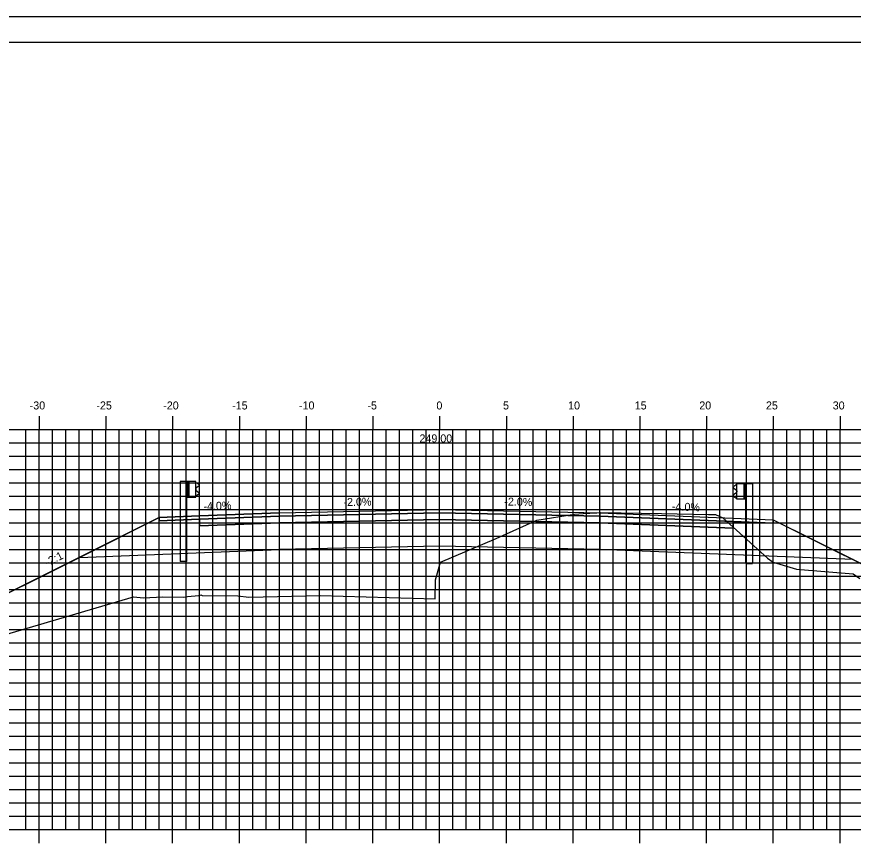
# Model space of a CAD drawing. Extents: x -22 to 1480, y -1511 to 8.
# Drawn here: x 378.2 to 440.9, y -1463.6 to -1401.4 of the extents above; entities that cross this region are included whole.
import ezdxf

# ---------------------------------------------------------------- set-up
doc = ezdxf.new("R2010")
doc.units = 0
for name, color, linetype in [('ANNOTATION', 7, 'Continuous'), ('BORDER', 7, 'Continuous'), ('D_Guardrail_Beam_Lt', 7, 'Continuous'), ('D_Guardrail_Beam_Rt', 7, 'Continuous'), ('D_Roadway_Centerline', 7, 'Continuous'), ('D_Roadway_Centerline_Text', 7, 'Continuous'), ('D_Roadway_Edge_Shoulder', 7, 'Continuous'), ('D_Roadway_Edge_TW', 7, 'Continuous'), ('D_Roadway_Pavement', 7, 'Continuous'), ('D_Roadway_SlopeLines', 7, 'Continuous'), ('D_Roadway_SubGrade', 7, 'Continuous'), ('H_V ANNOTATION', 7, 'Continuous'), ('MAJOR', 7, 'Continuous'), ('MINOR', 7, 'Continuous'), ('PLOT BOUNDARY', 7, 'Continuous'), ('S_Roadway_Centerline', 7, 'Continuous')]:
    doc.layers.add(name, color=color, linetype=linetype)

msp = doc.modelspace()

# ---------------------------------------------------------------- linework, layer by layer
at = {"layer": 'BORDER'}
msp.add_line((494.913, -1403.331), (334.913, -1403.331), dxfattribs=at)
at = {"layer": 'D_Guardrail_Beam_Lt'}
for p, q in [((390.484, -1436.23), (390.484, -1442.23)), ((390.955, -1436.23), (390.484, -1436.23)), ((391.642, -1436.23), (390.955, -1436.23)), ((390.955, -1436.23), (390.955, -1437.397)), ((391.017, -1436.23), (391.017, -1437.397)), ((391.121, -1436.23), (391.121, -1437.397)), ((391.642, -1437.397), (391.642, -1436.23)), ((391.642, -1436.314), (391.716, -1436.328)), ((391.732, -1436.335), (391.876, -1436.435)), ((391.647, -1436.778), (391.647, -1436.849)), ((391.876, -1436.578), (391.68, -1436.714)), ((391.68, -1436.913), (391.876, -1437.049)), ((390.955, -1437.397), (391.642, -1437.397)), ((390.975, -1442.23), (390.975, -1437.397)), ((391.716, -1437.299), (391.642, -1437.314)), ((391.876, -1437.192), (391.732, -1437.292)), ((390.975, -1442.23), (390.484, -1442.23))]:
    msp.add_line(p, q, dxfattribs=at)
for centre, major_axis, start_param, end_param in [((391.708, -1436.369), (0.0417, 0), 0.959931, 1.376053), ((391.725, -1436.778), (-0.0789, 0), 5.323254, 6.283185), ((391.725, -1436.849), (-0.0789, 0), 6.283185, 7.243116), ((391.825, -1436.506), (0.0877, 0), 5.323254, 7.243116), ((391.708, -1437.258), (0.0417, 0), 4.907132, 5.323254), ((391.825, -1437.121), (0.0877, 0), 5.323254, 7.243116)]:
    msp.add_ellipse(centre, major_axis=major_axis, ratio=0.995501, start_param=start_param, end_param=end_param, dxfattribs=at)
at = {"layer": 'D_Guardrail_Beam_Rt'}
for p, q in [((432.184, -1436.39), (432.871, -1436.39)), ((432.184, -1437.557), (432.184, -1436.39)), ((432.705, -1436.39), (432.705, -1437.557)), ((432.809, -1436.39), (432.809, -1437.557)), ((432.871, -1436.39), (433.342, -1436.39)), ((432.871, -1436.39), (432.871, -1437.557)), ((433.342, -1436.39), (433.342, -1442.39)), ((432.094, -1436.495), (431.95, -1436.595)), ((431.95, -1436.738), (432.146, -1436.874)), ((432.184, -1436.474), (432.11, -1436.488)), ((432.179, -1436.938), (432.179, -1437.009)), ((432.146, -1437.073), (431.95, -1437.209)), ((431.95, -1437.352), (432.094, -1437.452)), ((432.11, -1437.459), (432.184, -1437.474)), ((432.871, -1437.557), (432.184, -1437.557)), ((432.85, -1442.39), (432.85, -1437.557)), ((432.85, -1442.39), (433.342, -1442.39))]:
    msp.add_line(p, q, dxfattribs=at)
for centre, major_axis, start_param, end_param in [((432.001, -1436.666), (-0.0877, 0), 5.323254, 7.243116), ((432.118, -1436.529), (-0.0417, 0), 4.907132, 5.323254), ((432.1, -1436.938), (0.0789, 0), 0, 0.959931), ((432.1, -1437.009), (0.0789, 0), 5.323254, 6.283185), ((432.001, -1437.281), (-0.0877, 0), 5.323254, 7.243116), ((432.118, -1437.418), (-0.0417, 0), 0.959931, 1.376053)]:
    msp.add_ellipse(centre, major_axis=major_axis, ratio=0.995501, start_param=start_param, end_param=end_param, dxfattribs=at)
at = {"layer": 'D_Roadway_Centerline'}
msp.add_lwpolyline([(356.625, -1455.077), (360.465, -1453.158), (371.429, -1447.676), (374.305, -1446.237), (382.935, -1441.923), (388.913, -1438.934), (391.913, -1438.814), (397.913, -1438.574), (409.913, -1438.334), (421.913, -1438.574), (431.913, -1438.974), (434.913, -1439.094), (440.891, -1442.083), (456.487, -1449.881)], dxfattribs=at)
at = {"layer": 'D_Roadway_Edge_Shoulder'}
for points in [[(397.913, -1438.574), (391.913, -1438.814), (391.913, -1438.814), (388.913, -1438.934), (388.913, -1439.184), (391.913, -1439.064), (391.913, -1439.064), (397.913, -1438.824)], [(421.913, -1438.574), (431.913, -1438.974), (431.913, -1438.974), (434.913, -1439.094), (434.913, -1439.344), (431.913, -1439.224), (431.913, -1439.224), (421.913, -1438.824)]]:
    msp.add_lwpolyline(points, close=True, dxfattribs=at)
at = {"layer": 'D_Roadway_Edge_TW'}
msp.add_lwpolyline([(397.913, -1438.824), (397.913, -1438.574), (409.913, -1438.334), (421.913, -1438.574), (421.913, -1438.824), (409.913, -1438.584)], close=True, dxfattribs=at)
at = {"layer": 'D_Roadway_Pavement'}
for points in [[(397.913, -1438.824), (391.913, -1439.064), (391.913, -1439.064), (391.913, -1439.564), (397.913, -1439.324), (397.913, -1438.824)], [(421.913, -1438.824), (431.913, -1439.224), (431.913, -1439.224), (431.913, -1439.724), (421.913, -1439.324), (421.913, -1438.824)]]:
    msp.add_lwpolyline(points, dxfattribs=at)
msp.add_lwpolyline([(397.913, -1439.324), (397.913, -1438.824), (409.913, -1438.584), (421.913, -1438.824), (421.913, -1439.324), (409.913, -1439.084)], close=True, dxfattribs=at)
at = {"layer": 'D_Roadway_SlopeLines'}
for points in [[(388.913, -1438.934), (356.625, -1455.077)], [(434.913, -1439.094), (456.487, -1449.881)]]:
    msp.add_lwpolyline(points, dxfattribs=at)
at = {"layer": 'D_Roadway_SubGrade'}
for points in [[(397.913, -1439.324), (391.913, -1439.564), (391.913, -1439.064), (388.913, -1439.184), (388.913, -1438.934), (382.935, -1441.923), (397.913, -1441.324)], [(397.913, -1441.324), (397.913, -1439.324), (409.913, -1439.084), (421.913, -1439.324), (421.913, -1441.324), (409.913, -1441.084)], [(421.913, -1439.324), (431.913, -1439.724), (431.913, -1439.224), (434.913, -1439.344), (434.913, -1439.094), (440.891, -1442.083), (421.913, -1441.324)]]:
    msp.add_lwpolyline(points, close=True, dxfattribs=at)
at = {"layer": 'MAJOR'}
for p, q in [((379.913, -1431.329), (379.913, -1432.331)), ((384.913, -1431.329), (384.913, -1432.331)), ((389.913, -1431.329), (389.913, -1432.331)), ((394.913, -1431.329), (394.913, -1432.331)), ((399.913, -1431.329), (399.913, -1432.331)), ((404.913, -1431.329), (404.913, -1432.331)), ((409.913, -1431.329), (409.913, -1432.331)), ((414.913, -1431.329), (414.913, -1432.331)), ((419.913, -1431.329), (419.913, -1432.331)), ((424.913, -1431.329), (424.913, -1432.331)), ((429.913, -1431.329), (429.913, -1432.331)), ((434.913, -1431.329), (434.913, -1432.331)), ((439.913, -1431.329), (439.913, -1432.331)), ((339.913, -1432.331), (479.913, -1432.331)), ((339.913, -1432.331), (479.913, -1432.331)), ((379.913, -1462.331), (379.913, -1432.331)), ((384.913, -1462.331), (384.913, -1432.331)), ((389.913, -1462.331), (389.913, -1432.331)), ((394.913, -1462.331), (394.913, -1432.331)), ((399.913, -1462.331), (399.913, -1432.331)), ((404.913, -1462.331), (404.913, -1432.331)), ((409.913, -1462.331), (409.913, -1432.331)), ((414.913, -1462.331), (414.913, -1432.331)), ((419.913, -1462.331), (419.913, -1432.331)), ((424.913, -1462.331), (424.913, -1432.331)), ((429.913, -1462.331), (429.913, -1432.331)), ((434.913, -1462.331), (434.913, -1432.331)), ((439.913, -1462.331), (439.913, -1432.331)), ((339.913, -1437.331), (479.913, -1437.331)), ((339.913, -1442.331), (479.913, -1442.331)), ((339.913, -1447.331), (479.913, -1447.331)), ((339.913, -1452.331), (479.913, -1452.331)), ((339.913, -1457.331), (479.913, -1457.331)), ((339.913, -1462.331), (479.913, -1462.331)), ((339.913, -1462.331), (479.913, -1462.331)), ((379.913, -1463.333), (379.913, -1462.331)), ((384.913, -1463.333), (384.913, -1462.331)), ((389.913, -1463.333), (389.913, -1462.331)), ((394.913, -1463.333), (394.913, -1462.331)), ((399.913, -1463.333), (399.913, -1462.331)), ((404.913, -1463.333), (404.913, -1462.331)), ((409.913, -1463.333), (409.913, -1462.331)), ((414.913, -1463.333), (414.913, -1462.331)), ((419.913, -1463.333), (419.913, -1462.331)), ((424.913, -1463.333), (424.913, -1462.331)), ((429.913, -1463.333), (429.913, -1462.331)), ((434.913, -1463.333), (434.913, -1462.331)), ((439.913, -1463.333), (439.913, -1462.331))]:
    msp.add_line(p, q, dxfattribs=at)
at = {"layer": 'MINOR'}
for p, q in [((378.913, -1462.331), (378.913, -1432.331)), ((380.913, -1462.331), (380.913, -1432.331)), ((381.913, -1462.331), (381.913, -1432.331)), ((382.913, -1462.331), (382.913, -1432.331)), ((383.913, -1462.331), (383.913, -1432.331)), ((385.913, -1462.331), (385.913, -1432.331)), ((386.913, -1462.331), (386.913, -1432.331)), ((387.913, -1462.331), (387.913, -1432.331)), ((388.913, -1462.331), (388.913, -1432.331)), ((390.913, -1462.331), (390.913, -1432.331)), ((391.913, -1462.331), (391.913, -1432.331)), ((392.913, -1462.331), (392.913, -1432.331)), ((393.913, -1462.331), (393.913, -1432.331)), ((395.913, -1462.331), (395.913, -1432.331)), ((396.913, -1462.331), (396.913, -1432.331)), ((397.913, -1462.331), (397.913, -1432.331)), ((398.913, -1462.331), (398.913, -1432.331)), ((400.913, -1462.331), (400.913, -1432.331)), ((401.913, -1462.331), (401.913, -1432.331)), ((402.913, -1462.331), (402.913, -1432.331)), ((403.913, -1462.331), (403.913, -1432.331)), ((405.913, -1462.331), (405.913, -1432.331)), ((406.913, -1462.331), (406.913, -1432.331)), ((407.913, -1462.331), (407.913, -1432.331)), ((408.913, -1462.331), (408.913, -1432.331)), ((410.913, -1462.331), (410.913, -1432.331)), ((411.913, -1462.331), (411.913, -1432.331)), ((412.913, -1462.331), (412.913, -1432.331)), ((413.913, -1462.331), (413.913, -1432.331)), ((415.913, -1462.331), (415.913, -1432.331)), ((416.913, -1462.331), (416.913, -1432.331)), ((417.913, -1462.331), (417.913, -1432.331)), ((418.913, -1462.331), (418.913, -1432.331)), ((420.913, -1462.331), (420.913, -1432.331)), ((421.913, -1462.331), (421.913, -1432.331)), ((422.913, -1462.331), (422.913, -1432.331)), ((423.913, -1462.331), (423.913, -1432.331)), ((425.913, -1462.331), (425.913, -1432.331)), ((426.913, -1462.331), (426.913, -1432.331)), ((427.913, -1462.331), (427.913, -1432.331)), ((428.913, -1462.331), (428.913, -1432.331)), ((430.913, -1462.331), (430.913, -1432.331)), ((431.913, -1462.331), (431.913, -1432.331)), ((432.913, -1462.331), (432.913, -1432.331)), ((433.913, -1462.331), (433.913, -1432.331)), ((435.913, -1462.331), (435.913, -1432.331)), ((436.913, -1462.331), (436.913, -1432.331)), ((437.913, -1462.331), (437.913, -1432.331)), ((438.913, -1462.331), (438.913, -1432.331)), ((339.913, -1433.331), (479.913, -1433.331)), ((339.913, -1434.331), (479.913, -1434.331)), ((339.913, -1435.331), (479.913, -1435.331)), ((339.913, -1436.331), (479.913, -1436.331)), ((339.913, -1438.331), (479.913, -1438.331)), ((339.913, -1439.331), (479.913, -1439.331)), ((339.913, -1440.331), (479.913, -1440.331)), ((339.913, -1441.331), (479.913, -1441.331)), ((339.913, -1443.331), (479.913, -1443.331)), ((339.913, -1444.331), (479.913, -1444.331)), ((339.913, -1445.331), (479.913, -1445.331)), ((339.913, -1446.331), (479.913, -1446.331)), ((339.913, -1448.331), (479.913, -1448.331)), ((339.913, -1449.331), (479.913, -1449.331)), ((339.913, -1450.331), (479.913, -1450.331)), ((339.913, -1451.331), (479.913, -1451.331)), ((339.913, -1453.331), (479.913, -1453.331)), ((339.913, -1454.331), (479.913, -1454.331)), ((339.913, -1455.331), (479.913, -1455.331)), ((339.913, -1456.331), (479.913, -1456.331)), ((339.913, -1458.331), (479.913, -1458.331)), ((339.913, -1459.331), (479.913, -1459.331)), ((339.913, -1460.331), (479.913, -1460.331)), ((339.913, -1461.331), (479.913, -1461.331))]:
    msp.add_line(p, q, dxfattribs=at)
at = {"layer": 'PLOT BOUNDARY'}
msp.add_lwpolyline([(326.82, -1511.39), (496.82, -1511.39), (496.82, -1401.39), (326.82, -1401.39)], close=True, dxfattribs=at)
at = {"layer": 'S_Roadway_Centerline'}
msp.add_lwpolyline([(373.809, -1448.744), (386.991, -1444.884), (387.733, -1444.948), (389.169, -1444.89), (390.759, -1444.901), (391.027, -1444.865), (391.871, -1444.778), (391.927, -1444.742), (391.972, -1444.741), (392.014, -1444.729), (392.133, -1444.772), (394.786, -1444.799), (395.627, -1444.898), (400.975, -1444.777), (409.584, -1445.021), (409.601, -1443.6), (409.991, -1442.29), (414.137, -1440.499), (417.196, -1439.136), (420.015, -1438.677), (420.67, -1438.635), (421.692, -1438.569), (421.983, -1438.55), (426.53, -1438.643), (430.049, -1438.704), (430.592, -1438.711), (431.136, -1438.945), (434.478, -1441.973), (434.894, -1442.291), (436.64, -1442.813), (440.884, -1443.152), (441.391, -1443.513)], dxfattribs=at)

# ---------------------------------------------------------------- texts
at = {"layer": 'ANNOTATION'}
for s, rotation, p in [('-2.0%', 1.14576, (402.716, -1438.077)), ('-2.0%', 358.85424, (414.756, -1438.03)), ('-4.0%', 2.29061, (392.229, -1438.4)), ('-4.0%', 357.70939, (427.309, -1438.389)), ('-2:1', 26.56505, (380.538, -1442.603))]:
    msp.add_text(s, height=0.6, rotation=rotation, dxfattribs=at).set_placement(p)
at = {"layer": 'D_Roadway_Centerline'}
for s, p in [('C', (409.908, -1438.334)), ('L', (409.913, -1438.341))]:
    msp.add_text(s, height=0.0146, dxfattribs=at).set_placement(p)
at = {"layer": 'D_Roadway_Centerline_Text'}
msp.add_text('249.00', height=0.6, dxfattribs=at).set_placement((408.404, -1433.302))
at = {"layer": 'H_V ANNOTATION'}
for s, p in [('-30', (379.201, -1430.831)), ('-25', (384.198, -1430.831)), ('-20', (389.206, -1430.831)), ('-15', (394.37, -1430.831)), ('-10', (399.378, -1430.831)), ('-5', (404.504, -1430.831)), ('0', (409.672, -1430.831)), ('5', (414.664, -1430.831)), ('10', (419.538, -1430.831)), ('15', (424.53, -1430.831)), ('20', (429.367, -1430.831)), ('25', (434.359, -1430.831)), ('30', (439.362, -1430.831))]:
    msp.add_text(s, height=0.6, dxfattribs=at).set_placement(p)

doc.saveas('drawing.dxf')
